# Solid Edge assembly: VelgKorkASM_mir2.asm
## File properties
Author: KULL
Template: Iso Metric Assembly.asm
Last saved by: KULL
Revision: 2
Application: Solid Edge
Username: KULL
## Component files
Velg2_mir2.par
VeljekorkASM_mir2.asm
Rehv1_mir2.par
VelgKorkASM.asm
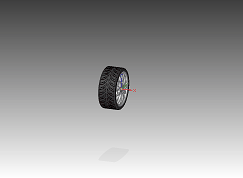
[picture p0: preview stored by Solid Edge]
